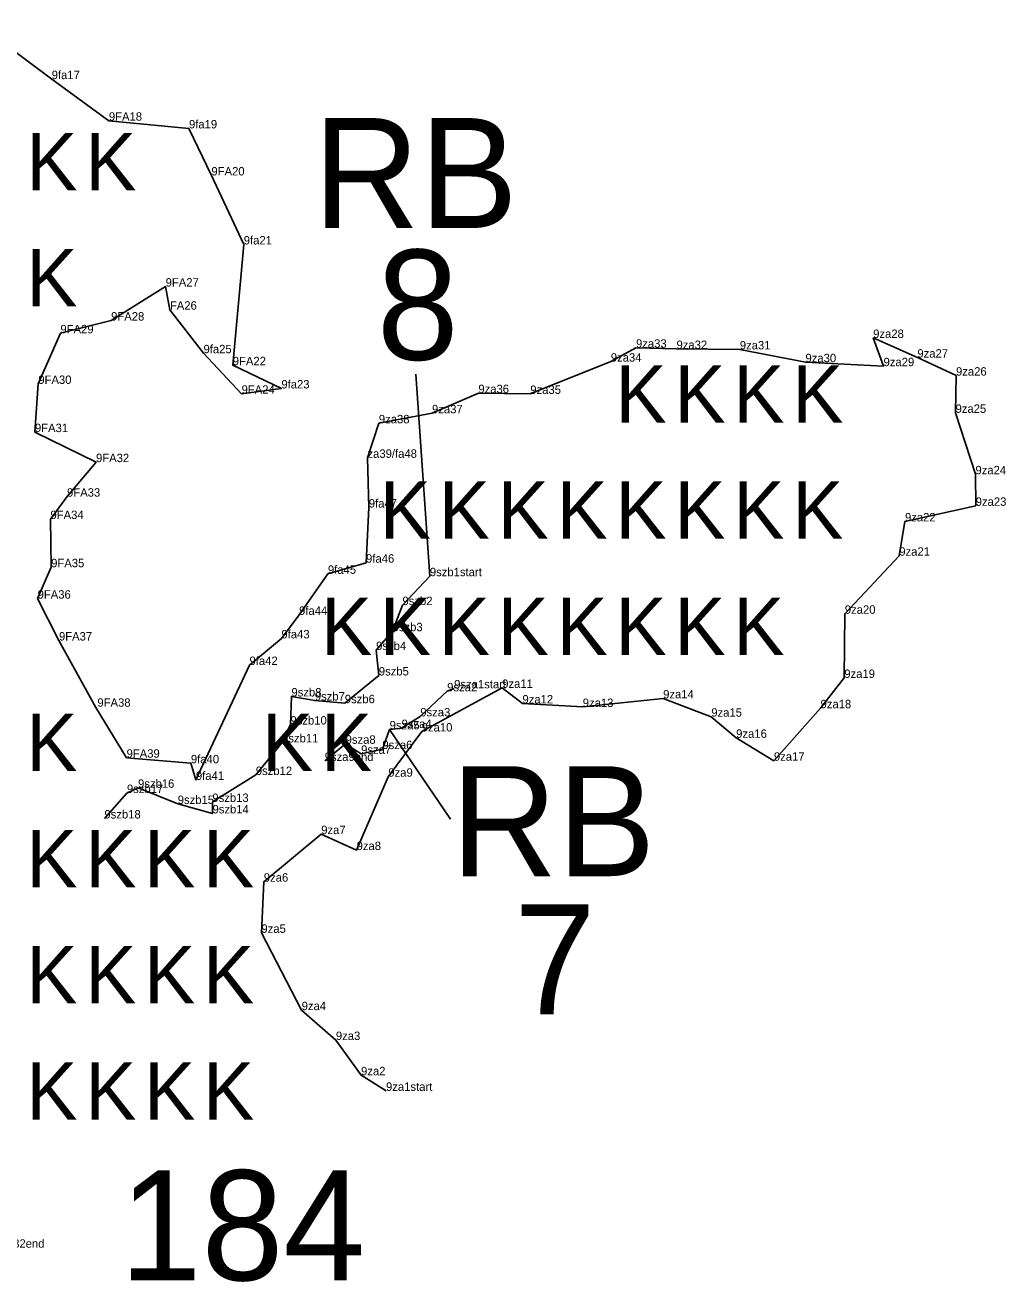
# Model space of a CAD drawing. Extents: x 2072529 to 2268812, y 436423 to 470008.
# Drawn here: x 2212614 to 2213196, y 449099 to 449846 of the extents above; entities that cross this region are included whole.
import ezdxf

# ---------------------------------------------------------------- set-up
doc = ezdxf.new("R2010")
doc.units = 0
for name, color, linetype in [('Old_Level_10', 7, 'Continuous'), ('Old_Level_20', 7, 'Continuous'), ('Old_Level_52', 7, 'Continuous'), ('Old_Level_55', 7, 'Continuous'), ('Old_Level_60', 7, 'Continuous'), ('Old_Level_62', 7, 'Continuous')]:
    doc.layers.add(name, color=color, linetype=linetype)

msp = doc.modelspace()

# ---------------------------------------------------------------- linework, layer by layer
at = {"layer": 'Old_Level_10'}
for points in [[(2212854.218, 449518.406), (2212837.945, 449501.256), (2212832.086, 449485.737), (2212822.295, 449474.542), (2212823.875, 449459.457), (2212803.687, 449442.983), (2212785.861, 449444.565), (2212771.981, 449446.988), (2212771.394, 449430.277), (2212766.401, 449419.678), (2212750.818, 449400.347), (2212724.998, 449384.316), (2212725.104, 449377.517), (2212704.43, 449383.115), (2212680.837, 449392.738), (2212674.252, 449389.637), (2212660.869, 449374.501)], [(2212868.658, 449451.793), (2212864.496, 449450.03), (2212848.518, 449435.14), (2212837.402, 449428.218), (2212830.298, 449427.437), (2212826.015, 449415.733), (2212813.376, 449412.912), (2212804.163, 449418.875), (2212791.739, 449408.663)]]:
    msp.add_lwpolyline(points, dxfattribs=at)
at = {"layer": 'Old_Level_20'}
for p, q in [((2212629.547, 449813.654), (2212629.547, 449813.654)), ((2212629.547, 449813.654), (2212629.547, 449813.654)), ((2212663.533, 449788.953), (2212663.533, 449788.953)), ((2212711.111, 449784.379), (2212711.111, 449784.379)), ((2212711.111, 449784.379), (2212711.111, 449784.379)), ((2212724.443, 449756.427), (2212724.443, 449756.427)), ((2212743.641, 449715.458), (2212743.641, 449715.458)), ((2212743.641, 449715.458), (2212743.641, 449715.458)), ((2212697.24, 449690.424), (2212697.24, 449690.424)), ((2212699.781, 449676.715), (2212699.781, 449676.715)), ((2212664.855, 449670.246), (2212664.855, 449670.246)), ((2212634.731, 449662.669), (2212634.731, 449662.669)), ((2212976.665, 449654.114), (2212976.665, 449654.114)), ((2213117.566, 449659.91), (2213117.566, 449659.91)), ((2213117.566, 449659.91), (2213117.566, 449659.91)), ((2212719.735, 449650.825), (2212719.735, 449650.825)), ((2212719.735, 449650.825), (2212719.735, 449650.825)), ((2213000.738, 449653.363), (2213000.738, 449653.363)), ((2213000.738, 449653.363), (2213000.738, 449653.363)), ((2213038.35, 449653.103), (2213038.35, 449653.103)), ((2213143.826, 449648.246), (2213143.826, 449648.246)), ((2212737.138, 449643.699), (2212737.138, 449643.699)), ((2212961.721, 449645.84), (2212961.721, 449645.84)), ((2212961.721, 449645.84), (2212961.721, 449645.84)), ((2213077.358, 449645.494), (2213077.358, 449645.494)), ((2213077.358, 449645.494), (2213077.358, 449645.494)), ((2213123.727, 449643.143), (2213123.727, 449643.143)), ((2212621.602, 449632.607), (2212621.602, 449632.607)), ((2213166.774, 449637.54), (2213166.774, 449637.54)), ((2213166.774, 449637.54), (2213166.774, 449637.54)), ((2212742.36, 449626.793), (2212742.36, 449626.793)), ((2212766.005, 449629.922), (2212766.005, 449629.922)), ((2212766.005, 449629.922), (2212766.005, 449629.922)), ((2212883.014, 449627.147), (2212883.014, 449627.147)), ((2212913.884, 449626.687), (2212913.884, 449626.687)), ((2212823.909, 449609.212), (2212823.909, 449609.212)), ((2212823.909, 449609.212), (2212823.909, 449609.212)), ((2212855.486, 449615.151), (2212855.486, 449615.151)), ((2213166.506, 449615.44), (2213166.506, 449615.44)), ((2212619.591, 449603.987), (2212619.591, 449603.987)), ((2212817.153, 449588.726), (2212817.153, 449588.726)), ((2212655.879, 449586.161), (2212655.879, 449586.161)), ((2213178.331, 449578.931), (2213178.331, 449578.931)), ((2213178.331, 449578.931), (2213178.331, 449578.931)), ((2212638.683, 449565.651), (2212638.683, 449565.651)), ((2212817.94, 449559.178), (2212817.94, 449559.178)), ((2213178.475, 449560.218), (2213178.475, 449560.218)), ((2213178.475, 449560.218), (2213178.475, 449560.218)), ((2212628.831, 449552.363), (2212628.831, 449552.363)), ((2213136.447, 449550.946), (2213136.447, 449550.946)), ((2213136.447, 449550.946), (2213136.447, 449550.946)), ((2213133.078, 449530.561), (2213133.078, 449530.561)), ((2212629.234, 449523.732), (2212629.234, 449523.732)), ((2212793.64, 449519.821), (2212793.64, 449519.821)), ((2212816.315, 449526.447), (2212816.315, 449526.447)), ((2212854.218, 449518.406), (2212854.218, 449518.406)), ((2212621.181, 449505.084), (2212621.181, 449505.084)), ((2212837.945, 449501.256), (2212837.945, 449501.256)), ((2212776.518, 449495.434), (2212776.518, 449495.434)), ((2212776.518, 449495.434), (2212776.518, 449495.434)), ((2213100.734, 449496.094), (2213100.734, 449496.094)), ((2213100.734, 449496.094), (2213100.734, 449496.094)), ((2212832.086, 449485.737), (2212832.086, 449485.737)), ((2212633.875, 449480.207), (2212633.875, 449480.207)), ((2212766.041, 449481.465), (2212766.041, 449481.465)), ((2212822.295, 449474.542), (2212822.295, 449474.542)), ((2212747.075, 449465.663), (2212747.075, 449465.663)), ((2212747.075, 449465.663), (2212747.075, 449465.663)), ((2212823.875, 449459.457), (2212823.875, 449459.457)), ((2213100.408, 449457.992), (2213100.408, 449457.992)), ((2212771.981, 449446.988), (2212771.981, 449446.988)), ((2212864.496, 449450.03), (2212864.496, 449450.03)), ((2212868.658, 449451.793), (2212868.658, 449451.793)), ((2212897.189, 449452.066), (2212897.189, 449452.066)), ((2212897.189, 449452.066), (2212897.189, 449452.066)), ((2212992.799, 449445.828), (2212992.799, 449445.828)), ((2212992.799, 449445.828), (2212992.799, 449445.828)), ((2212655.735, 449440.429), (2212655.735, 449440.429)), ((2212785.861, 449444.565), (2212785.861, 449444.565)), ((2212803.687, 449442.983), (2212803.687, 449442.983)), ((2212909.227, 449442.824), (2212909.227, 449442.824)), ((2212909.227, 449442.824), (2212909.227, 449442.824)), ((2212945.031, 449440.723), (2212945.031, 449440.723)), ((2212945.031, 449440.723), (2212945.031, 449440.723)), ((2213086.316, 449439.987), (2213086.316, 449439.987)), ((2213086.316, 449439.987), (2213086.316, 449439.987)), ((2212771.394, 449430.277), (2212771.394, 449430.277)), ((2212848.518, 449435.14), (2212848.518, 449435.14)), ((2213021.388, 449434.967), (2213021.388, 449434.967)), ((2212830.298, 449427.437), (2212830.298, 449427.437)), ((2212837.402, 449428.218), (2212837.402, 449428.218)), ((2212849.362, 449426.173), (2212849.362, 449426.173)), ((2212849.362, 449426.173), (2212849.362, 449426.173)), ((2212766.401, 449419.678), (2212766.401, 449419.678)), ((2212804.163, 449418.875), (2212804.163, 449418.875)), ((2212826.015, 449415.733), (2212826.015, 449415.733)), ((2213036.184, 449422.415), (2213036.184, 449422.415)), ((2212674.033, 449410.614), (2212674.033, 449410.614)), ((2212791.739, 449408.663), (2212791.739, 449408.663)), ((2212813.376, 449412.912), (2212813.376, 449412.912)), ((2213058.593, 449408.805), (2213058.593, 449408.805)), ((2212712.253, 449407.286), (2212712.253, 449407.286)), ((2212712.253, 449407.286), (2212712.253, 449407.286)), ((2212750.818, 449400.347), (2212750.818, 449400.347)), ((2212680.837, 449392.738), (2212680.837, 449392.738)), ((2212715.22, 449397.42), (2212715.22, 449397.42)), ((2212829.539, 449399.319), (2212829.539, 449399.319)), ((2212674.252, 449389.637), (2212674.252, 449389.637)), ((2212704.43, 449383.115), (2212704.43, 449383.115)), ((2212724.998, 449384.316), (2212724.998, 449384.316)), ((2212660.869, 449374.501), (2212660.869, 449374.501)), ((2212725.104, 449377.517), (2212725.104, 449377.517)), ((2212789.675, 449365.225), (2212789.675, 449365.225)), ((2212810.7, 449355.75), (2212810.7, 449355.75)), ((2212810.7, 449355.75), (2212810.7, 449355.75)), ((2212755.557, 449336.975), (2212755.557, 449336.975)), ((2212755.557, 449336.975), (2212755.557, 449336.975)), ((2212754.153, 449306.593), (2212754.153, 449306.593)), ((2212778.029, 449260.672), (2212778.029, 449260.672)), ((2212778.029, 449260.672), (2212778.029, 449260.672)), ((2212798.388, 449242.925), (2212798.388, 449242.925)), ((2212813.334, 449221.973), (2212813.334, 449221.973)), ((2212813.334, 449221.973), (2212813.334, 449221.973)), ((2212828.161, 449212.719), (2212828.161, 449212.719))]:
    msp.add_line(p, q, dxfattribs=at)
at = {"layer": 'Old_Level_52'}
msp.add_lwpolyline([(2212586.393, 449845.717), (2212629.547, 449813.654), (2212663.533, 449788.953), (2212711.111, 449784.379), (2212724.443, 449756.427), (2212743.641, 449715.458), (2212737.138, 449643.699), (2212766.005, 449629.922), (2212742.36, 449626.793), (2212719.735, 449650.825), (2212699.781, 449676.715), (2212697.24, 449690.424), (2212664.855, 449670.246), (2212634.731, 449662.669), (2212621.602, 449632.607), (2212619.591, 449603.987), (2212655.879, 449586.161), (2212638.683, 449565.651), (2212628.831, 449552.363), (2212629.234, 449523.732), (2212621.181, 449505.084), (2212633.875, 449480.207), (2212655.735, 449440.429), (2212674.033, 449410.614), (2212712.253, 449407.286), (2212715.22, 449397.42), (2212747.075, 449465.663), (2212766.041, 449481.465), (2212776.518, 449495.434), (2212793.64, 449519.821), (2212816.315, 449526.447), (2212817.94, 449559.178), (2212817.153, 449588.726), (2212823.909, 449609.212), (2212855.486, 449615.151), (2212883.014, 449627.147), (2212913.884, 449626.687), (2212961.721, 449645.84), (2212976.665, 449654.114), (2213000.738, 449653.363), (2213038.35, 449653.103), (2213077.358, 449645.494), (2213123.727, 449643.143), (2213117.566, 449659.91), (2213143.826, 449648.246), (2213166.774, 449637.54), (2213166.506, 449615.44), (2213178.331, 449578.931), (2213178.475, 449560.218), (2213136.447, 449550.946), (2213133.078, 449530.561), (2213100.734, 449496.094), (2213100.408, 449457.992), (2213086.316, 449439.987), (2213058.593, 449408.805), (2213036.184, 449422.415), (2213021.388, 449434.967), (2212992.799, 449445.828), (2212945.031, 449440.723), (2212909.227, 449442.824), (2212897.189, 449452.066), (2212849.362, 449426.173), (2212829.539, 449399.319), (2212810.7, 449355.75), (2212789.675, 449365.225), (2212755.557, 449336.975), (2212754.153, 449306.593), (2212778.029, 449260.672), (2212798.388, 449242.925), (2212813.334, 449221.973), (2212828.161, 449212.719)], dxfattribs=at)
at = {"layer": 'Old_Level_62'}
for p, q in [((2212845.802, 449638.34), (2212854.218, 449518.406)), ((2212866.487, 449374.143), (2212830.298, 449427.437))]:
    msp.add_line(p, q, dxfattribs=at)

# ---------------------------------------------------------------- texts
at = {"layer": 'Old_Level_55'}
for p in [(2212614.499, 449747.69), (2212649.499, 449747.69), (2212614.499, 449678.69), (2212964.499, 449609.69), (2212999.499, 449609.69), (2213034.499, 449609.69), (2213069.499, 449609.69), (2212824.499, 449540.69), (2212859.499, 449540.69), (2212894.499, 449540.69), (2212929.499, 449540.69), (2212964.499, 449540.69), (2212999.499, 449540.69), (2213034.499, 449540.69), (2213069.499, 449540.69), (2212789.499, 449471.69), (2212824.499, 449471.69), (2212859.499, 449471.69), (2212894.499, 449471.69), (2212929.499, 449471.69), (2212964.499, 449471.69), (2212999.499, 449471.69), (2213034.499, 449471.69), (2212614.499, 449402.69), (2212754.499, 449402.69), (2212789.499, 449402.69), (2212614.499, 449333.69), (2212649.499, 449333.69), (2212684.499, 449333.69), (2212719.499, 449333.69), (2212614.499, 449264.69), (2212649.499, 449264.69), (2212684.499, 449264.69), (2212719.499, 449264.69), (2212614.499, 449195.69), (2212649.499, 449195.69), (2212684.499, 449195.69), (2212719.499, 449195.69)]:
    msp.add_text('K', height=34, dxfattribs=at).set_placement(p)
at = {"layer": 'Old_Level_60'}
for s, p in [('9fa17', (2212629.547, 449813.654)), ('9fa17', (2212629.547, 449813.654)), ('9FA18', (2212663.533, 449788.953)), ('9fa19', (2212711.111, 449784.379)), ('9fa19', (2212711.111, 449784.379)), ('9FA20', (2212724.443, 449756.427)), ('9fa21', (2212743.641, 449715.458)), ('9fa21', (2212743.641, 449715.458)), ('9FA27', (2212697.24, 449690.424)), ('FA26', (2212699.781, 449676.715)), ('9FA28', (2212664.855, 449670.246)), ('9FA29', (2212634.731, 449662.669)), ('9za28', (2213117.566, 449659.91)), ('9za28', (2213117.566, 449659.91)), ('9fa25', (2212719.735, 449650.825)), ('9fa25', (2212719.735, 449650.825)), ('9za33', (2212976.665, 449654.114)), ('9za32', (2213000.738, 449653.363)), ('9za32', (2213000.738, 449653.363)), ('9za31', (2213038.35, 449653.103)), ('9FA22', (2212737.138, 449643.699)), ('9za34', (2212961.721, 449645.84)), ('9za34', (2212961.721, 449645.84)), ('9za30', (2213077.358, 449645.494)), ('9za30', (2213077.358, 449645.494)), ('9za29', (2213123.727, 449643.143)), ('9za27', (2213143.826, 449648.246)), ('9za26', (2213166.774, 449637.54)), ('9za26', (2213166.774, 449637.54)), ('9FA30', (2212621.602, 449632.607)), ('9FA24', (2212742.36, 449626.793)), ('9fa23', (2212766.005, 449629.922)), ('9fa23', (2212766.005, 449629.922)), ('9za36', (2212883.014, 449627.147)), ('9za35', (2212913.884, 449626.687)), ('9za37', (2212855.486, 449615.151)), ('9za25', (2213166.506, 449615.44)), ('9za38', (2212823.909, 449609.212)), ('9za38', (2212823.909, 449609.212)), ('9FA31', (2212619.591, 449603.987)), ('9FA32', (2212655.879, 449586.161)), ('za39/fa48', (2212817.153, 449588.726)), ('9za24', (2213178.331, 449578.931)), ('9za24', (2213178.331, 449578.931)), ('9FA33', (2212638.683, 449565.651)), ('9fa47', (2212817.94, 449559.178)), ('9za23', (2213178.475, 449560.218)), ('9za23', (2213178.475, 449560.218)), ('9FA34', (2212628.831, 449552.363)), ('9za22', (2213136.447, 449550.946)), ('9za22', (2213136.447, 449550.946)), ('9za21', (2213133.078, 449530.561)), ('9FA35', (2212629.234, 449523.732)), ('9fa46', (2212816.315, 449526.447)), ('9fa45', (2212793.64, 449519.821)), ('9szb1start', (2212854.218, 449518.406)), ('9FA36', (2212621.181, 449505.084)), ('9szb2', (2212837.945, 449501.256)), ('9fa44', (2212776.518, 449495.434)), ('9fa44', (2212776.518, 449495.434)), ('9za20', (2213100.734, 449496.094)), ('9za20', (2213100.734, 449496.094)), ('9szb3', (2212832.086, 449485.737)), ('9FA37', (2212633.875, 449480.207)), ('9fa43', (2212766.041, 449481.465)), ('9szb4', (2212822.295, 449474.542)), ('9fa42', (2212747.075, 449465.663)), ('9fa42', (2212747.075, 449465.663)), ('9szb5', (2212823.875, 449459.457)), ('9za19', (2213100.408, 449457.992)), ('9sza2', (2212864.496, 449450.03)), ('9sza1start', (2212868.658, 449451.793)), ('9za11', (2212897.189, 449452.066)), ('9za11', (2212897.189, 449452.066)), ('9FA38', (2212656.7, 449440.878)), ('9szb8', (2212771.981, 449446.988)), ('9szb7', (2212785.861, 449444.565)), ('9szb6', (2212803.687, 449442.983)), ('9za12', (2212909.227, 449442.824)), ('9za12', (2212909.227, 449442.824)), ('9za13', (2212945.031, 449440.723)), ('9za13', (2212945.031, 449440.723)), ('9za14', (2212992.799, 449445.828)), ('9za14', (2212992.799, 449445.828)), ('9za18', (2213086.316, 449439.987)), ('9za18', (2213086.316, 449439.987)), ('9sza3', (2212848.518, 449435.14)), ('9za15', (2213021.388, 449434.967)), ('9szb10', (2212771.394, 449430.277)), ('9sza5', (2212830.298, 449427.437)), ('9sza4', (2212837.402, 449428.218)), ('9za10', (2212849.362, 449426.173)), ('9za10', (2212849.362, 449426.173)), ('9szb11', (2212766.401, 449419.678)), ('9sza8', (2212804.163, 449418.875)), ('9za16', (2213036.184, 449422.415)), ('9FA39', (2212674.033, 449410.614)), ('9sza7', (2212813.376, 449412.912)), ('9sza6', (2212826.015, 449415.733)), ('9fa40', (2212712.253, 449407.286)), ('9fa40', (2212712.253, 449407.286)), ('9sza9end', (2212791.739, 449408.663)), ('9za17', (2213058.593, 449408.805)), ('9fa41', (2212715.22, 449397.42)), ('9szb12', (2212750.818, 449400.347)), ('9za9', (2212829.539, 449399.319)), ('9szb17', (2212674.252, 449389.637)), ('9szb16', (2212680.837, 449392.738)), ('9szb15', (2212704.43, 449383.115)), ('9szb13', (2212724.998, 449384.316)), ('9szb18', (2212660.869, 449374.501)), ('9szb14', (2212725.104, 449377.517)), ('9za7', (2212789.675, 449365.225)), ('9za8', (2212810.7, 449355.75)), ('9za8', (2212810.7, 449355.75)), ('9za6', (2212755.557, 449336.975)), ('9za6', (2212755.557, 449336.975)), ('9za5', (2212754.153, 449306.593)), ('9za4', (2212778.029, 449260.672)), ('9za4', (2212778.029, 449260.672)), ('9za3', (2212798.388, 449242.925)), ('9za2', (2212813.334, 449221.973)), ('9za2', (2212813.334, 449221.973)), ('9za1start', (2212828.161, 449212.719)), ('9wa32end', (2212594.408, 449119.559))]:
    msp.add_text(s, height=5, dxfattribs=at).set_placement(p)
at = {"layer": 'Old_Level_62'}
for s, p in [('RB', (2212785.013, 449725.183)), ('8', (2212822.707, 449646.965)), ('RB', (2212866.777, 449340.231)), ('7', (2212904.215, 449258.252)), ('184', (2212670.031, 449100.207))]:
    msp.add_text(s, height=65.34, dxfattribs=at).set_placement(p)

doc.saveas('drawing.dxf')
